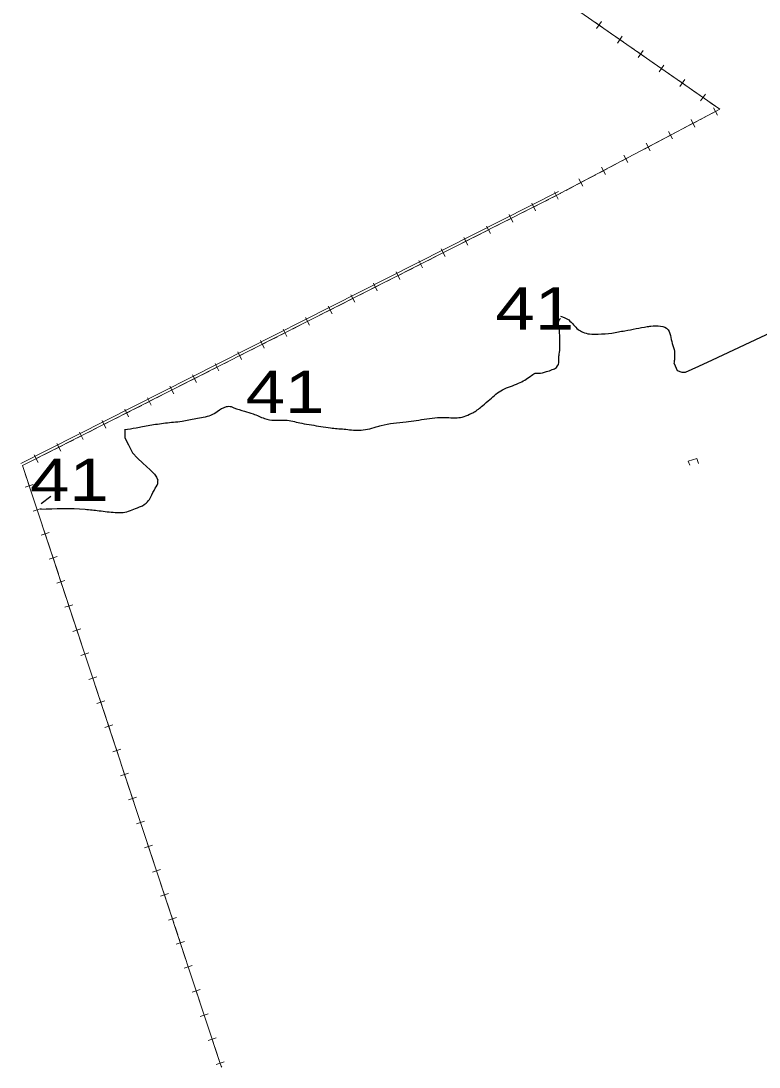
# Model space of a CAD drawing. Extents: x 476989 to 498418, y 4381813 to 4416555.
# Drawn here: x 483464 to 484337, y 4384130 to 4385368 of the extents above; entities that cross this region are included whole.
import ezdxf
from ezdxf.enums import TextEntityAlignment as Align

# ---------------------------------------------------------------- set-up
doc = ezdxf.new("R2010")
doc.units = 0
doc.header["$LTSCALE"] = 20
doc.linetypes.add('MEDIUM_DASHED', pattern=[4.5, 3, -1.5])
for name, color, linetype, lineweight in [('13', 7, 'Continuous', 13), ('34', 7, 'Continuous', 13), ('48', 7, 'MEDIUM_DASHED', 13), ('6', 7, 'Continuous', 25)]:
    doc.layers.add(name, color=color, linetype=linetype, lineweight=lineweight)

msp = doc.modelspace()

# ---------------------------------------------------------------- linework, layer by layer
at = {"layer": '34'}
for p, q in [((484144.02, 4385366.41), (484152.23, 4385360.7)), ((484145.27, 4385359.45), (484150.98, 4385367.66)), ((484156.33, 4385357.84), (484164.53, 4385352.12)), ((484168.64, 4385349.26), (484176.84, 4385343.55)), ((484169.88, 4385342.3), (484175.6, 4385350.51)), ((484180.94, 4385340.69), (484189.15, 4385334.97)), ((484193.25, 4385332.11), (484201.46, 4385326.4)), ((484194.49, 4385325.15), (484200.21, 4385333.36)), ((484205.56, 4385323.54), (484213.76, 4385317.82)), ((484217.86, 4385314.96), (484226.07, 4385309.24)), ((484219.11, 4385308), (484224.83, 4385316.21)), ((484230.17, 4385306.39), (484238.38, 4385300.67)), ((484242.48, 4385297.81), (484250.68, 4385292.09)), ((484243.72, 4385290.85), (484249.44, 4385299.05)), ((484254.79, 4385289.23), (484262.99, 4385283.52)), ((484267.09, 4385280.66), (484275.3, 4385274.94)), ((484268.34, 4385273.7), (484274.05, 4385281.9)), ((484279.4, 4385272.08), (484287.6, 4385266.37)), ((484290.24, 4385263.6), (484281.4, 4385258.92)), ((484283.48, 4385265.68), (484288.16, 4385256.84)), ((484263.72, 4385249.57), (484254.88, 4385244.89)), ((484256.96, 4385251.65), (484261.64, 4385242.81)), ((484276.98, 4385256.58), (484268.14, 4385251.91)), ((484237.21, 4385235.54), (484228.37, 4385230.86)), ((484230.45, 4385237.62), (484235.12, 4385228.78)), ((484250.46, 4385242.55), (484241.62, 4385237.88)), ((484203.93, 4385223.59), (484208.61, 4385214.75)), ((484223.95, 4385228.52), (484215.11, 4385223.85)), ((484197.43, 4385214.49), (484188.59, 4385209.82)), ((484210.69, 4385221.51), (484201.85, 4385216.83)), ((484170.91, 4385200.46), (484162.07, 4385195.79)), ((484184.17, 4385207.48), (484175.33, 4385202.8)), ((484177.41, 4385209.56), (484182.09, 4385200.72)), ((484144.4, 4385186.43), (484135.56, 4385181.75)), ((484157.65, 4385193.45), (484148.82, 4385188.77)), ((484150.9, 4385195.53), (484155.57, 4385186.69)), ((484131.14, 4385179.42), (484122.3, 4385174.74)), ((484124.38, 4385181.5), (484129.06, 4385172.66)), ((484100.12, 4385166.55), (483464.12, 4384844.55)), ((484100.12, 4385166.55), (483464.12, 4384844.55)), ((484102, 4385164), (483466, 4384842)), ((484102, 4385164), (484093.09, 4385159.49)), ((484099.81, 4385157.29), (484095.29, 4385166.21)), ((484102.72, 4385164.38), (484102, 4385164)), ((484102.72, 4385164.38), (484102, 4385164)), ((484104.62, 4385165.39), (484102.72, 4385164.38)), ((484117.88, 4385172.4), (484109.04, 4385167.72)), ((484075.25, 4385150.46), (484066.33, 4385145.94)), ((484073.05, 4385143.74), (484068.53, 4385152.66)), ((484088.63, 4385157.23), (484079.7, 4385152.71)), ((484048.5, 4385136.91), (484039.57, 4385132.39)), ((484046.29, 4385130.19), (484041.78, 4385139.11)), ((484061.87, 4385143.68), (484052.95, 4385139.17)), ((484021.74, 4385123.37), (484012.82, 4385118.85)), ((484019.54, 4385116.65), (484015.02, 4385125.57)), ((484035.11, 4385130.14), (484026.19, 4385125.62)), ((483992.78, 4385103.1), (483988.26, 4385112.02)), ((484008.36, 4385116.59), (483999.44, 4385112.07)), ((483966.03, 4385089.55), (483961.51, 4385098.47)), ((483981.6, 4385103.04), (483972.68, 4385098.53)), ((483994.98, 4385109.82), (483986.06, 4385105.3)), ((483954.85, 4385089.5), (483945.92, 4385084.98)), ((483968.23, 4385096.27), (483959.31, 4385091.76)), ((483928.09, 4385075.95), (483919.17, 4385071.43)), ((483941.47, 4385082.73), (483932.55, 4385078.21)), ((483939.27, 4385076.01), (483934.75, 4385084.93)), ((483901.33, 4385062.4), (483892.41, 4385057.89)), ((483914.72, 4385069.18), (483905.79, 4385064.66)), ((483912.51, 4385062.46), (483908, 4385071.38)), ((483887.96, 4385055.63), (483879.04, 4385051.12)), ((483885.76, 4385048.91), (483881.24, 4385057.84)), ((483861.2, 4385042.09), (483852.28, 4385037.57)), ((483859, 4385035.37), (483854.48, 4385044.29)), ((483874.58, 4385048.86), (483865.65, 4385044.34)), ((483834.45, 4385028.54), (483825.52, 4385024.02)), ((483832.24, 4385021.82), (483827.73, 4385030.74)), ((483847.82, 4385035.31), (483838.9, 4385030.79)), ((483807.69, 4385014.99), (483798.77, 4385010.48)), ((483805.49, 4385008.27), (483800.97, 4385017.2)), ((483821.06, 4385021.77), (483812.14, 4385017.25)), ((483780.93, 4385001.45), (483772.01, 4384996.93)), ((483778.73, 4384994.73), (483774.21, 4385003.65)), ((483794.31, 4385008.22), (483785.39, 4385003.7)), ((483754.18, 4384987.9), (483745.26, 4384983.38)), ((483751.98, 4384981.18), (483747.46, 4384990.1)), ((483767.55, 4384994.67), (483758.63, 4384990.16)), ((483725.22, 4384967.64), (483720.7, 4384976.56)), ((483740.8, 4384981.13), (483731.87, 4384976.61)), ((483698.46, 4384954.09), (483693.95, 4384963.01)), ((483714.04, 4384967.58), (483705.12, 4384963.06)), ((483727.42, 4384974.36), (483718.5, 4384969.84)), ((483687.28, 4384954.03), (483678.36, 4384949.52)), ((483700.67, 4384960.81), (483691.74, 4384956.29)), ((483660.53, 4384940.49), (483651.61, 4384935.97)), ((483673.91, 4384947.26), (483664.99, 4384942.75)), ((483671.71, 4384940.54), (483667.19, 4384949.46)), ((483633.77, 4384926.94), (483624.85, 4384922.42)), ((483647.15, 4384933.72), (483638.23, 4384929.2)), ((483644.95, 4384927), (483640.43, 4384935.92)), ((483607.01, 4384913.39), (483598.09, 4384908.88)), ((483620.4, 4384920.17), (483611.48, 4384915.65)), ((483618.19, 4384913.45), (483613.68, 4384922.37)), ((483593.64, 4384906.62), (483584.72, 4384902.11)), ((483591.44, 4384899.9), (483586.92, 4384908.83)), ((483566.88, 4384893.08), (483557.96, 4384888.56)), ((483564.68, 4384886.36), (483560.17, 4384895.28)), ((483580.26, 4384899.85), (483571.34, 4384895.33)), ((483540.13, 4384879.53), (483531.21, 4384875.01)), ((483537.93, 4384872.81), (483533.41, 4384881.73)), ((483553.5, 4384886.3), (483544.58, 4384881.78)), ((483513.37, 4384865.98), (483504.45, 4384861.47)), ((483511.17, 4384859.26), (483506.65, 4384868.19)), ((483526.75, 4384872.75), (483517.82, 4384868.24)), ((483486.62, 4384852.44), (483477.69, 4384847.92)), ((483484.41, 4384845.72), (483479.9, 4384854.64)), ((483499.99, 4384859.21), (483491.07, 4384854.69)), ((483473.23, 4384845.66), (483466, 4384842)), ((483466, 4384842), (483699.09, 4384136.76)), ((483467.57, 4384837.25), (483470.71, 4384827.76)), ((483469.1, 4384816.69), (483478.59, 4384819.83)), ((483472.28, 4384823.01), (483475.41, 4384813.52)), ((483476.98, 4384808.77), (483480.12, 4384799.27)), ((483478.51, 4384788.21), (483488.01, 4384791.35)), ((483481.69, 4384794.53), (483484.83, 4384785.03)), ((483486.4, 4384780.28), (483489.54, 4384770.79)), ((483491.11, 4384766.04), (483494.24, 4384756.55)), ((483487.93, 4384759.72), (483497.42, 4384762.86)), ((483495.81, 4384751.8), (483498.95, 4384742.3)), ((483497.34, 4384731.24), (483506.84, 4384734.38)), ((483500.52, 4384737.56), (483503.66, 4384728.06)), ((483505.23, 4384723.31), (483508.37, 4384713.82)), ((483506.76, 4384702.76), (483516.25, 4384705.89)), ((483509.94, 4384709.07), (483513.07, 4384699.58)), ((483514.64, 4384694.83), (483517.78, 4384685.34)), ((483516.17, 4384674.27), (483525.67, 4384677.41)), ((483519.35, 4384680.59), (483522.49, 4384671.09)), ((483524.06, 4384666.35), (483527.2, 4384656.85)), ((483525.59, 4384645.79), (483535.08, 4384648.93)), ((483528.76, 4384652.1), (483531.9, 4384642.61)), ((483533.47, 4384637.86), (483536.61, 4384628.37)), ((483535, 4384617.3), (483544.5, 4384620.44)), ((483538.18, 4384623.62), (483541.32, 4384614.12)), ((483542.89, 4384609.38), (483546.02, 4384599.88)), ((483544.42, 4384588.82), (483553.91, 4384591.96)), ((483547.59, 4384595.13), (483550.73, 4384585.64)), ((483552.3, 4384580.89), (483555.44, 4384571.4)), ((483557.01, 4384566.65), (483560.15, 4384557.16)), ((483553.83, 4384560.33), (483563.33, 4384563.47)), ((483561.72, 4384552.41), (483564.85, 4384542.91)), ((483563.25, 4384531.85), (483572.74, 4384534.99)), ((483566.42, 4384538.17), (483569.56, 4384528.67)), ((483571.13, 4384523.92), (483574.27, 4384514.43)), ((483572.66, 4384503.36), (483582.15, 4384506.5)), ((483575.84, 4384509.68), (483578.98, 4384500.19)), ((483580.55, 4384495.44), (483583.68, 4384485.94)), ((483585.25, 4384481.2), (483588.39, 4384471.7)), ((483582.07, 4384474.88), (483591.57, 4384478.02)), ((483589.96, 4384466.95), (483593.1, 4384457.46)), ((483591.49, 4384446.4), (483600.98, 4384449.53)), ((483594.67, 4384452.71), (483597.81, 4384443.22)), ((483599.37, 4384438.47), (483602.51, 4384428.98)), ((483600.9, 4384417.91), (483610.4, 4384421.05)), ((483604.08, 4384424.23), (483607.22, 4384414.73)), ((483608.79, 4384409.99), (483611.93, 4384400.49)), ((483610.32, 4384389.43), (483619.81, 4384392.57)), ((483613.5, 4384395.74), (483616.64, 4384386.25)), ((483618.2, 4384381.5), (483621.34, 4384372.01)), ((483619.73, 4384360.94), (483629.23, 4384364.08)), ((483622.91, 4384367.26), (483626.05, 4384357.76)), ((483627.62, 4384353.02), (483630.76, 4384343.52)), ((483629.15, 4384332.46), (483638.64, 4384335.6)), ((483632.33, 4384338.77), (483635.46, 4384329.28)), ((483637.03, 4384324.53), (483640.17, 4384315.04)), ((483638.56, 4384303.97), (483648.06, 4384307.11)), ((483641.74, 4384310.29), (483644.88, 4384300.8)), ((483646.45, 4384296.05), (483649.59, 4384286.55)), ((483651.16, 4384281.81), (483654.29, 4384272.31)), ((483647.98, 4384275.49), (483657.47, 4384278.63)), ((483655.86, 4384267.56), (483659, 4384258.07)), ((483657.39, 4384247), (483666.89, 4384250.14)), ((483660.57, 4384253.32), (483663.71, 4384243.83)), ((483665.28, 4384239.08), (483668.42, 4384229.58)), ((483666.81, 4384218.52), (483676.3, 4384221.66)), ((483669.98, 4384224.84), (483673.12, 4384215.34)), ((483674.69, 4384210.59), (483677.83, 4384201.1)), ((483679.4, 4384196.35), (483682.54, 4384186.86)), ((483676.22, 4384190.04), (483685.72, 4384193.17)), ((483684.11, 4384182.11), (483687.25, 4384172.62)), ((483685.64, 4384161.55), (483695.13, 4384164.69)), ((483688.81, 4384167.87), (483691.95, 4384158.37)), ((483693.52, 4384153.63), (483696.66, 4384144.13)), ((483695.05, 4384133.07), (483704.55, 4384136.21)), ((483698.23, 4384139.38), (483699.09, 4384136.76))]:
    msp.add_line(p, q, dxfattribs=at)
for points in [[(484103.22, 4385394.84), (484291, 4385264), (484102.72, 4385164.38)], [(483699.09, 4384136.76), (483701, 4384131), (483701.64, 4384130.02)]]:
    msp.add_lwpolyline(points, dxfattribs=at)
at = {"layer": '48'}
msp.add_lwpolyline([(484265.71, 4384844.4), (484263.66, 4384850.43), (484253.69, 4384847.41), (484255.71, 4384842.64)], dxfattribs=at)
at = {"layer": '6'}
msp.add_line((483487.94, 4384797.22), (483499.52, 4384805.78), dxfattribs=at)
for points in [[(484459.08, 4385019.18), (484455.39, 4385016.01), (484448.82, 4385016.01), (484436.64, 4385020.7), (484429.76, 4385025.69), (484424.76, 4385032.25), (484421.64, 4385032.25), (484282.12, 4384967.05), (484265.88, 4384959.56), (484249.94, 4384952.38), (484246.29, 4384952.07), (484240.98, 4384954.25), (484237.23, 4384962.37)], [(483587.08, 4384884.42), (483587.05, 4384881.67), (483587.05, 4384875.1), (483591.44, 4384866.7), (483596.19, 4384857.2), (483602.04, 4384850.99), (483608.25, 4384844.79), (483617.02, 4384837.12), (483622.14, 4384832), (483624.7, 4384828.35), (483626.16, 4384824.7)]]:
    msp.add_lwpolyline(points, dxfattribs=at)
for points in [[(484072.71, 4384951.59), (484076.5, 4384951.46), (484085.91, 4384953.29), (484092.76, 4384955.65), (484097.86, 4384958.35), (484100.69, 4384966.27), (484100.68, 4384971.57), (484101.12, 4384973.91), (484101.59, 4384983.01), (484101.76, 4384992.72), (484101.64, 4384996.31), (484100.61, 4385007.16), (484100.17, 4385012.34), (484102.4, 4385016.18)], [(484102.41, 4385018.95), (484112.24, 4385014.43), (484123.49, 4385003.19), (484128.93, 4385000.06), (484136.94, 4384997.86), (484147.17, 4384997.68), (484163.2, 4384999.01), (484178.72, 4385001.76), (484191.97, 4385004.19), (484205.12, 4385006.55), (484209.27, 4385007.05), (484220.87, 4385007.19), (484229.91, 4385002.93), (484233.01, 4384993.54), (484235.57, 4384984.24), (484237.09, 4384979.61), (484237.41, 4384971.23), (484237.15, 4384965.97), (484236.81, 4384962.99)], [(483716.09, 4384910.37), (483728.56, 4384906.5), (483738.81, 4384903.36), (483752.37, 4384897.87), (483764.13, 4384895.72), (483779.16, 4384895.71), (483796.36, 4384892.11), (483807.84, 4384890.22), (483830.33, 4384886.7), (483846.47, 4384885.23), (483863.98, 4384883.97), (483884.43, 4384887.78), (483890.35, 4384889.54), (483919.76, 4384893.88), (483931.93, 4384895.43), (483957.16, 4384898.9), (483978.14, 4384898.71), (483986.19, 4384899.52), (483994.88, 4384902.79), (484000, 4384905.38), (484010.44, 4384913.01), (484018.97, 4384920.5), (484033.93, 4384931.86), (484052.96, 4384939.49), (484067.04, 4384947.89), (484072.38, 4384951.59)], [(483716.44, 4384910.09), (483713.2, 4384911.45), (483706.93, 4384911.47), (483696.46, 4384905.89), (483688.57, 4384901.53), (483670.94, 4384897.44), (483654.77, 4384894.2), (483644.64, 4384893.16), (483625.55, 4384890.89), (483607.97, 4384887.86), (483600.49, 4384886.38), (483586.8, 4384884.38)], [(483487.33, 4384790.49), (483540.08, 4384790.42), (483556.51, 4384788.6), (483575.76, 4384786.62), (483585.08, 4384786.62), (483601.9, 4384792.09), (483605.46, 4384793.49), (483613.98, 4384799.33), (483617.78, 4384805.09), (483622.97, 4384815.2), (483626.22, 4384822.95), (483626.1, 4384824.59)]]:
    msp.add_spline(points, degree=3, dxfattribs=at)

# ---------------------------------------------------------------- texts
at = {"layer": '13', "width": 1.25}
for p in [(484072.15, 4385003.14), (483776.57, 4384904.3), (483521.45, 4384800.16)]:
    msp.add_text('41', height=50, dxfattribs=at).set_placement(p, align=Align.CENTER)

doc.saveas('drawing.dxf')
